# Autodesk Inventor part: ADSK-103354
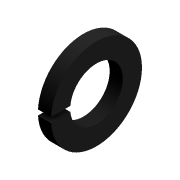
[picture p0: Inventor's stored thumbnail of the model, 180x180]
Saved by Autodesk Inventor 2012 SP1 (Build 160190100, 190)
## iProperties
Created: 2000-08
Part Number: ADSK-103354
Description: Helical Spring Lock Washer
Document SubType Name: Modeling
Standard: ASME B18.21.1 - 1/2 Regular. Carbon Steel
Designer: gao
Density: 1 g/cm^3
Material: Default
Control State: 0
Master: False
Checked Out: False
Shininess: 0.0
Density: 0.0
Volumn: 0.0
Area: 0.0
PropertySet Name: Model Information
Author: gao
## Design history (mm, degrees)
node "Base1"
body "Solid1"
